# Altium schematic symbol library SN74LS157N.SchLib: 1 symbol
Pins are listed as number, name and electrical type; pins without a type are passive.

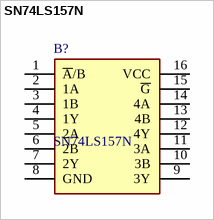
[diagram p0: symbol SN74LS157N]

## SN74LS157N
designator B?
Quadruple 2-Line To 1-Line Data Selectors/Multiplexers; Manufacturer_Name: Texas Instruments; Geometry.Height: 5.08mm
footprint DIP794W53P254L1930H508Q16N
pins: 1 ~{A}/B, 2 1A, 3 1B, 4 1Y, 5 2A, 6 2B, 7 2Y, 8 GND, 9 3Y, 10 3B, 11 3A, 12 4Y, 13 4B, 14 4A, 15 ~{G}, 16 VCC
